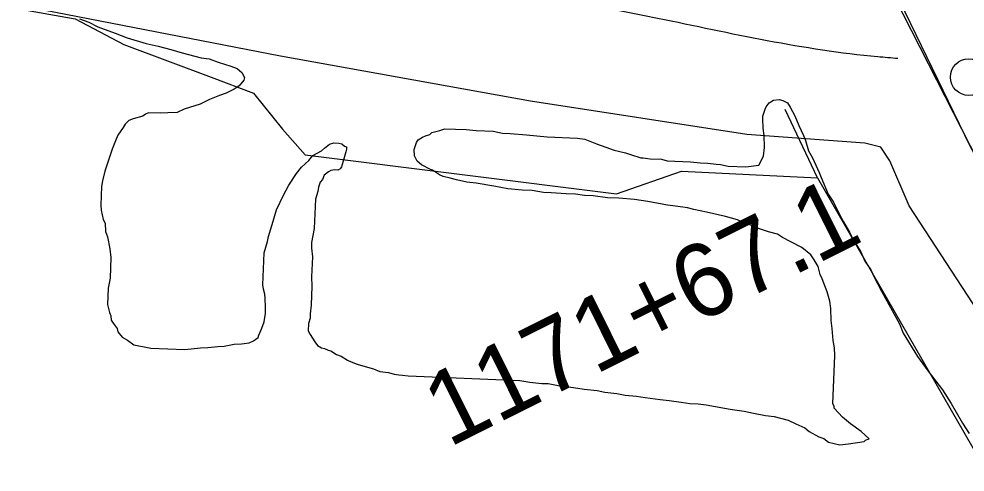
# Model space of a CAD drawing. Extents: x 3161514 to 3199414, y 831166 to 856601.
# Drawn here: x 3184047 to 3185339, y 837386 to 838004 of the extents above; entities that cross this region are included whole.
import ezdxf

# ---------------------------------------------------------------- set-up
doc = ezdxf.new("R2010")
doc.units = 0
for name, color, linetype in [('V-LEVE-TOET', 7, 'Continuous'), ('V-RAIL-TRAK', 7, 'Continuous'), ('V-ROAD-CNTR', 7, 'Continuous'), ('V-SITE-VEGE', 7, 'Continuous'), ('V-SURV-IDEN', 7, 'Continuous'), ('V-SURV-LINE', 7, 'Continuous'), ('V-TOPO-SHOR', 7, 'Continuous')]:
    doc.layers.add(name, color=color, linetype=linetype)

msp = doc.modelspace()

# ---------------------------------------------------------------- linework, layer by layer
at = {"layer": 'V-LEVE-TOET'}
msp.add_lwpolyline([(3185479.9, 837402), (3185378.5, 837572.4), (3185263.2, 837749.1), (3185236.4, 837810.4), (3185224.1, 837829.2), (3185202.7, 837834.6), (3185041.5, 837846.4), (3184746, 837891.8), (3184404.6, 837953.3), (3183911.8, 838049.4), (3183641.4, 838109.2), (3183369.5, 838165.1), (3183020.2, 838213.8), (3182646.2, 838283.9), (3182335, 838338.5), (3181981.1, 838407.4), (3181709.1, 838448.9), (3181476.7, 838488.3), (3181216.9, 838495.2), (3181043.3, 838497.2), (3180895.4, 838492), (3180760.8, 838480.3)], dxfattribs=at)
at = {"layer": 'V-RAIL-TRAK'}
msp.add_line((3184059.2, 840354.1), (3185467.8, 837592.3), dxfattribs=at)
at = {"layer": 'V-ROAD-CNTR'}
msp.add_lwpolyline([(3182510, 843255.2), (3182750, 842829.8), (3182962.8, 842459.6), (3183082.3, 842242.1), (3183216.7, 842004.2), (3183348.4, 841767.1), (3183502.7, 841469.7), (3183666.2, 841147.6), (3183851.3, 840779.3), (3184016.5, 840444.7), (3184210.8, 840064.8), (3184373.6, 839736.8), (3184597.6, 839309.2), (3184736.6, 839033.3), (3184901.3, 838718.9), (3185039.4, 838447.7), (3185242.5, 838044.4), (3185345.9, 837830.9), (3185543.6, 837469.6), (3185705.5, 837185.2), (3185948.9, 836754.5), (3186048.4, 836579.3)], dxfattribs=at)
msp.add_spline([(3185247.7, 837950), (3185220.1, 837952.3), (3184919.5, 838004.8), (3184339.6, 838108.5), (3183779, 838207.2), (3183367, 838284.1), (3182794.1, 838383.3), (3182428.7, 838447.8), (3182275.5, 838472.5), (3181998.8, 838523), (3181803.1, 838555.1), (3181641.5, 838586.6), (3181550.7, 838598.2), (3181445.6, 838611.4), (3181325.6, 838620), (3181174.8, 838631.9), (3181016.7, 838639.1), (3180880.4, 838632.5), (3180707.8, 838613), (3180579.6, 838596.6), (3180431.4, 838569.9), (3180332.4, 838547.3), (3180171.1, 838506.1), (3180026.7, 838458.9), (3179877.5, 838403.8), (3179654.2, 838294.6), (3179462.8, 838196.9), (3179346.3, 838121.9), (3179173.3, 838003.7), (3178965.2, 837857.6), (3178757.9, 837712.7), (3178391.8, 837460.5), (3178085.3, 837254.5), (3177675.2, 836977.6), (3177220.5, 836675.6), (3177123, 836609.3)], degree=3, dxfattribs=at)
at = {"layer": 'V-SITE-VEGE'}
for p, q in [((3184130.2, 838004), (3184142.7, 837999.7)), ((3184142.7, 837999.7), (3184155.1, 837993.4)), ((3184155.1, 837993.4), (3184179, 837984.6)), ((3184179, 837984.6), (3184195.3, 837978.2)), ((3184195.3, 837978.2), (3184221.2, 837970.4)), ((3184221.2, 837970.4), (3184237.6, 837966.8)), ((3184237.6, 837966.8), (3184255, 837962.2)), ((3184255, 837962.2), (3184270.3, 837957.8)), ((3184270.3, 837957.8), (3184296.3, 837950.9)), ((3184296.3, 837950.9), (3184307, 837949.5)), ((3184307, 837949.5), (3184319.4, 837945.2)), ((3184319.4, 837945.2), (3184336.7, 837939.6)), ((3184336.7, 837939.6), (3184345.4, 837936.4)), ((3184345.4, 837936.4), (3184352, 837931.2)), ((3184352, 837931.2), (3184355.6, 837924.3)), ((3184354.5, 837920.5), (3184348.3, 837912.9)), ((3184355.6, 837924.3), (3184354.5, 837920.5)), ((3184330.4, 837902.9), (3184321.5, 837899.4)), ((3184341.3, 837908.3), (3184330.4, 837902.9)), ((3184348.3, 837912.9), (3184341.3, 837908.3)), ((3184307.7, 837894.1), (3184294.8, 837887.8)), ((3184321.5, 837899.4), (3184307.7, 837894.1)), ((3185067.7, 837884), (3185071.8, 837889.6)), ((3185071.8, 837889.6), (3185077.8, 837893.3)), ((3185077.8, 837893.3), (3185085.6, 837894)), ((3185085.6, 837894), (3185090.4, 837892.8)), ((3185090.4, 837892.8), (3185097.1, 837889.6)), ((3185097.1, 837889.6), (3185100.7, 837883.6)), ((3184224.4, 837875.9), (3184220.4, 837874.1)), ((3184240.9, 837875.3), (3184224.4, 837875.9)), ((3184250.6, 837875.9), (3184240.9, 837875.3)), ((3184263.3, 837876.4), (3184250.6, 837875.9)), ((3184273.2, 837880.8), (3184263.3, 837876.4)), ((3184294.8, 837887.8), (3184273.2, 837880.8)), ((3185063.3, 837871.5), (3185066.6, 837881.1)), ((3185066.6, 837881.1), (3185067.7, 837884)), ((3185100.7, 837883.6), (3185107.1, 837871.7)), ((3184197.7, 837865.3), (3184192.7, 837860.6)), ((3184203.6, 837868), (3184197.7, 837865.3)), ((3184216.4, 837871.4), (3184203.6, 837868)), ((3184220.4, 837874.1), (3184216.4, 837871.4)), ((3185063.2, 837867.6), (3185063.3, 837871.5)), ((3185063.6, 837854.9), (3185063.2, 837867.6)), ((3185107.1, 837871.7), (3185112.4, 837858.9)), ((3184189.6, 837855.9), (3184182.4, 837845.5)), ((3184192.7, 837860.6), (3184189.6, 837855.9)), ((3184611.3, 837849.2), (3184622.1, 837851.7)), ((3184622.1, 837851.7), (3184629, 837854.3)), ((3184629, 837854.3), (3184658.1, 837853.2)), ((3184658.1, 837853.2), (3184671.7, 837851.7)), ((3184671.7, 837851.7), (3184695, 837850.8)), ((3184695, 837850.8), (3184707.5, 837848.4)), ((3185065.2, 837845.2), (3185063.6, 837854.9)), ((3185112.4, 837858.9), (3185118.7, 837845)), ((3184179.1, 837837.8), (3184174.8, 837826.3)), ((3184182.4, 837845.5), (3184179.1, 837837.8)), ((3184590.3, 837835.4), (3184592.4, 837839.2)), ((3184592.4, 837839.2), (3184598.4, 837842.9)), ((3184598.4, 837842.9), (3184602.4, 837844.7)), ((3184602.4, 837844.7), (3184608.3, 837846.4)), ((3184608.3, 837846.4), (3184611.3, 837849.2)), ((3184707.5, 837848.4), (3184718.2, 837848)), ((3184718.2, 837848), (3184740.5, 837846.1)), ((3184740.5, 837846.1), (3184768.6, 837843.1)), ((3184768.6, 837843.1), (3184810.3, 837841.5)), ((3184810.3, 837841.5), (3184820, 837840.1)), ((3184820, 837840.1), (3184836.3, 837833.6)), ((3185065.5, 837828.6), (3185065.2, 837845.2)), ((3185118.7, 837845), (3185121.3, 837838.1)), ((3185121.3, 837838.1), (3185125.6, 837824.3)), ((3184174.8, 837826.3), (3184172.6, 837819.6)), ((3184448.7, 837817.6), (3184460.6, 837824)), ((3184460.6, 837824), (3184464.6, 837827.7)), ((3184464.6, 837827.7), (3184471.6, 837833.2)), ((3184471.6, 837833.2), (3184477.5, 837835)), ((3184477.5, 837835), (3184484.3, 837834.7)), ((3184484.3, 837834.7), (3184488.2, 837833.6)), ((3184488.2, 837833.6), (3184491.9, 837830.5)), ((3184491.9, 837830.5), (3184494.8, 837829.4)), ((3184494.7, 837826.5), (3184493.6, 837822.7)), ((3184494.8, 837829.4), (3184494.7, 837826.5)), ((3184587, 837825.8), (3184590.3, 837835.4)), ((3184587.7, 837817.1), (3184587, 837825.8)), ((3184836.3, 837833.6), (3184848.7, 837829.3)), ((3184848.7, 837829.3), (3184860.2, 837824.9)), ((3184860.2, 837824.9), (3184875.6, 837821.4)), ((3185064.1, 837817), (3185065.5, 837828.6)), ((3185125.6, 837824.3), (3185131.1, 837814.4)), ((3184172.6, 837819.6), (3184168.2, 837807.1)), ((3184433.5, 837801.7), (3184443.5, 837811)), ((3184443.5, 837811), (3184448.7, 837817.6)), ((3184491.3, 837813), (3184487.9, 837802.5)), ((3184493.6, 837822.7), (3184491.3, 837813)), ((3184591.3, 837810.1), (3184587.7, 837817.1)), ((3184875.6, 837821.4), (3184882.4, 837819.2)), ((3184882.4, 837819.2), (3184896.8, 837814.8)), ((3184896.8, 837814.8), (3184899.7, 837814.6)), ((3184899.7, 837814.6), (3184909.4, 837813.3)), ((3184909.4, 837813.3), (3184924.9, 837812.7)), ((3184924.9, 837812.7), (3184932.6, 837810.5)), ((3185057.8, 837804.6), (3185064.1, 837817)), ((3185131.1, 837814.4), (3185140, 837794.6)), ((3184168.2, 837807.1), (3184164.9, 837796.6)), ((3184426.3, 837793.2), (3184433.5, 837801.7)), ((3184479, 837798), (3184473.1, 837797.2)), ((3184482.9, 837797.8), (3184479, 837798)), ((3184485.9, 837799.6), (3184482.9, 837797.8)), ((3184487.9, 837802.5), (3184485.9, 837799.6)), ((3184596.9, 837805), (3184591.3, 837810.1)), ((3184609.3, 837798.7), (3184596.9, 837805)), ((3184612.2, 837797.6), (3184609.3, 837798.7)), ((3184932.6, 837810.5), (3184964.6, 837809.2)), ((3184964.6, 837809.2), (3184978.2, 837807.7)), ((3184978.2, 837807.7), (3184987.9, 837807.3)), ((3184987.9, 837807.3), (3184999.5, 837805.9)), ((3184999.5, 837805.9), (3185005.3, 837805.7)), ((3185005.3, 837805.7), (3185015.9, 837803.3)), ((3185015.9, 837803.3), (3185040.2, 837802.4)), ((3185040.2, 837802.4), (3185057.8, 837804.6)), ((3184164.9, 837796.6), (3184161.5, 837783.1)), ((3184416, 837777.1), (3184426.3, 837793.2)), ((3184464.1, 837790.8), (3184462, 837785)), ((3184470.2, 837795.4), (3184464.1, 837790.8)), ((3184473.1, 837797.2), (3184470.2, 837795.4)), ((3184621.7, 837791.4), (3184612.2, 837797.6)), ((3184626.5, 837789.3), (3184621.7, 837791.4)), ((3184636.1, 837787), (3184626.5, 837789.3)), ((3184644.8, 837784.7), (3184636.1, 837787)), ((3185140, 837794.6), (3185142.7, 837787.7)), ((3185142.7, 837787.7), (3185152.5, 837764.9)), ((3184160.2, 837775.4), (3184159.2, 837750.1)), ((3184161.5, 837783.1), (3184160.2, 837775.4)), ((3184408.6, 837763.7), (3184416, 837777.1)), ((3184456.7, 837774.5), (3184455.5, 837768.7)), ((3184458.9, 837781.2), (3184456.7, 837774.5)), ((3184462, 837785), (3184458.9, 837781.2)), ((3184659.2, 837781.2), (3184644.8, 837784.7)), ((3184671.8, 837779.8), (3184659.2, 837781.2)), ((3184695.9, 837775.9), (3184671.8, 837779.8)), ((3184715.2, 837772.2), (3184695.9, 837775.9)), ((3184734.6, 837770.5), (3184715.2, 837772.2)), ((3184399.1, 837743.7), (3184408.6, 837763.7)), ((3184455.5, 837768.7), (3184452.2, 837758.2)), ((3184748.2, 837770), (3184734.6, 837770.5)), ((3184763.7, 837767.4), (3184748.2, 837770)), ((3184774.4, 837767), (3184763.7, 837767.4)), ((3184794.7, 837765.3), (3184774.4, 837767)), ((3184807.3, 837764.8), (3184794.7, 837765.3)), ((3184819.9, 837763.3), (3184807.3, 837764.8)), ((3184831.6, 837762.8), (3184819.9, 837763.3)), ((3184850.9, 837760.2), (3184831.6, 837762.8)), ((3184866.4, 837759.5), (3184850.9, 837760.2)), ((3184887.8, 837757.7), (3184866.4, 837759.5)), ((3185152.5, 837764.9), (3185159.9, 837754)), ((3184159.2, 837750.1), (3184159.9, 837743.3)), ((3184452.2, 837758.2), (3184450.6, 837718.4)), ((3184906.1, 837755.1), (3184887.8, 837757.7)), ((3184933.2, 837750.1), (3184906.1, 837755.1)), ((3184943.8, 837748.8), (3184933.2, 837750.1)), ((3184960.2, 837746.2), (3184943.8, 837748.8)), ((3185159.9, 837754), (3185167.9, 837737.1)), ((3184159.9, 837743.3), (3184162.3, 837730.5)), ((3184394.6, 837728.3), (3184399.1, 837743.7)), ((3184968.9, 837743.9), (3184960.2, 837746.2)), ((3184986.2, 837740.3), (3184968.9, 837743.9)), ((3185012.3, 837734.4), (3184986.2, 837740.3)), ((3185028.6, 837729.9), (3185012.3, 837734.4)), ((3185167.9, 837737.1), (3185173.4, 837727.2)), ((3184162.3, 837730.5), (3184165.1, 837725.6)), ((3184165.1, 837725.6), (3184165.6, 837713.9)), ((3184388, 837707.2), (3184394.6, 837728.3)), ((3185035.3, 837726.7), (3185028.6, 837729.9)), ((3185047.8, 837722.4), (3185035.3, 837726.7)), ((3185054.5, 837719.2), (3185047.8, 837722.4)), ((3185173.4, 837727.2), (3185181.6, 837713.3)), ((3184165.6, 837713.9), (3184168.2, 837707)), ((3184450.6, 837718.4), (3184447, 837699.1)), ((3185070.8, 837713.7), (3185054.5, 837719.2)), ((3185083.3, 837710.3), (3185070.8, 837713.7)), ((3185089.9, 837706.1), (3185083.3, 837710.3)), ((3185181.6, 837713.3), (3185187, 837702.3)), ((3184168.2, 837707), (3184171.5, 837690.3)), ((3184382.2, 837685), (3184386.7, 837700.4)), ((3184386.7, 837700.4), (3184388, 837707.2)), ((3184447, 837699.1), (3184446.7, 837691.3)), ((3185101.4, 837699.8), (3185089.9, 837706.1)), ((3185116.6, 837692.4), (3185101.4, 837699.8)), ((3185187, 837702.3), (3185197.1, 837686.4)), ((3184171.5, 837690.3), (3184172.9, 837678.6)), ((3184380.5, 837641.4), (3184382.2, 837685)), ((3184446.7, 837691.3), (3184448.1, 837679.6)), ((3185128.9, 837682.2), (3185116.6, 837692.4)), ((3185133.5, 837675.3), (3185128.9, 837682.2)), ((3185197.1, 837686.4), (3185202.4, 837673.6)), ((3184172.9, 837678.6), (3184171.9, 837650.4)), ((3184448.1, 837679.6), (3184447.1, 837652.4)), ((3185138.9, 837666.3), (3185133.5, 837675.3)), ((3185202.4, 837673.6), (3185210.7, 837661.6)), ((3185141.4, 837655.5), (3185138.9, 837666.3)), ((3185210.7, 837661.6), (3185215.2, 837651.7)), ((3184171.9, 837650.4), (3184169.4, 837636.9)), ((3184447.1, 837652.4), (3184447.6, 837639.7)), ((3185144.1, 837649.6), (3185141.4, 837655.5)), ((3185151.2, 837631.8), (3185144.1, 837649.6)), ((3185215.2, 837651.7), (3185225.1, 837632.8)), ((3184169.4, 837636.9), (3184168.5, 837614.6)), ((3184381.3, 837635.5), (3184380.5, 837641.4)), ((3184383, 837628.6), (3184381.3, 837635.5)), ((3184447.6, 837639.7), (3184446.6, 837613.5)), ((3185154.6, 837619), (3185151.2, 837631.8)), ((3185225.1, 837632.8), (3185249.7, 837588.1)), ((3184383.7, 837622.8), (3184383, 837628.6)), ((3184384.2, 837611.1), (3184383.7, 837622.8)), ((3185156.2, 837609.2), (3185154.6, 837619)), ((3184168.5, 837614.6), (3184171, 837603.8)), ((3184383.9, 837602.3), (3184384.2, 837611.1)), ((3184446.6, 837613.5), (3184445.1, 837601.9)), ((3185156.5, 837592.7), (3185156.2, 837609.2)), ((3184171, 837603.8), (3184172.8, 837598.9)), ((3184172.8, 837598.9), (3184173.5, 837593)), ((3184173.5, 837593), (3184176.3, 837589)), ((3184382.5, 837590.7), (3184383.9, 837602.3)), ((3184444.9, 837596.1), (3184442.7, 837588.4)), ((3184445.1, 837601.9), (3184444.9, 837596.1)), ((3185158, 837581.9), (3185156.5, 837592.7)), ((3184176.3, 837589), (3184181.8, 837582)), ((3184181.8, 837582), (3184182.6, 837577.1)), ((3184375, 837572.5), (3184379.2, 837582.1)), ((3184379.2, 837582.1), (3184382.5, 837590.7)), ((3184442.7, 837588.4), (3184442.3, 837578.7)), ((3184442.3, 837578.7), (3184445, 837573.7)), ((3185159.3, 837565.4), (3185158, 837581.9)), ((3185249.7, 837588.1), (3185255, 837575.2)), ((3184182.6, 837577.1), (3184188.2, 837570.1)), ((3184188.2, 837570.1), (3184195.8, 837565.9)), ((3184195.8, 837565.9), (3184204.3, 837559.7)), ((3184367.9, 837565), (3184373.9, 837569.7)), ((3184373.9, 837569.7), (3184375, 837572.5)), ((3184445, 837573.7), (3184451.4, 837563.7)), ((3185255, 837575.2), (3185274.2, 837543.4)), ((3184204.3, 837559.7), (3184209.1, 837558.6)), ((3184209.1, 837558.6), (3184220.7, 837556.2)), ((3184220.7, 837556.2), (3184227.5, 837554.9)), ((3184227.5, 837554.9), (3184274, 837553.1)), ((3184274, 837553.1), (3184295.5, 837555.2)), ((3184295.5, 837555.2), (3184305.3, 837555.8)), ((3184305.3, 837555.8), (3184318.9, 837557.2)), ((3184318.9, 837557.2), (3184327.7, 837557.9)), ((3184327.7, 837557.9), (3184341.4, 837560.2)), ((3184341.4, 837560.2), (3184351.2, 837560.8)), ((3184351.2, 837560.8), (3184361.9, 837562.4)), ((3184361.9, 837562.4), (3184367.9, 837565)), ((3184451.4, 837563.7), (3184455.1, 837558.7)), ((3184455.1, 837558.7), (3184460.8, 837555.6)), ((3184460.8, 837555.6), (3184464.7, 837554.5)), ((3184464.7, 837554.5), (3184469.5, 837552.3)), ((3185160.9, 837555.6), (3185159.3, 837565.4)), ((3185161.4, 837544.9), (3185160.9, 837555.6)), ((3184469.5, 837552.3), (3184473.3, 837551.2)), ((3184473.3, 837551.2), (3184480.9, 837546.1)), ((3184480.9, 837546.1), (3184487.6, 837543.9)), ((3184487.6, 837543.9), (3184496.1, 837538.7)), ((3185158.9, 837478.8), (3185161.4, 837544.9)), ((3185274.2, 837543.4), (3185288.9, 837523.4)), ((3184496.1, 837538.7), (3184500.9, 837536.5)), ((3184500.9, 837536.5), (3184509.5, 837533.3)), ((3184509.5, 837533.3), (3184517.2, 837531)), ((3184517.2, 837531), (3184531.6, 837526.6)), ((3184531.6, 837526.6), (3184540.3, 837523.3)), ((3184540.3, 837523.3), (3184551.9, 837521.9)), ((3184551.9, 837521.9), (3184559.6, 837519.7)), ((3184559.6, 837519.7), (3184566.3, 837518.4)), ((3184566.3, 837518.4), (3184571.2, 837518.2)), ((3184571.2, 837518.2), (3184578.9, 837517)), ((3184578.9, 837517), (3184731.3, 837511)), ((3185288.9, 837523.4), (3185308.4, 837498.3)), ((3184731.3, 837511), (3184744.9, 837508.6)), ((3184744.9, 837508.6), (3184761.3, 837506.9)), ((3184761.3, 837506.9), (3184770.1, 837506.6)), ((3184770.1, 837506.6), (3184783.6, 837504.1)), ((3184783.6, 837504.1), (3184804.9, 837501.4)), ((3184804.9, 837501.4), (3184819.3, 837498.9)), ((3184819.3, 837498.9), (3184836.8, 837497.2)), ((3184836.8, 837497.2), (3184847.4, 837494.9)), ((3184847.4, 837494.9), (3184863.9, 837493.2)), ((3184863.9, 837493.2), (3184875.4, 837490.8)), ((3184875.4, 837490.8), (3184890.9, 837489.3)), ((3184890.9, 837489.3), (3184902.5, 837487.8)), ((3185308.4, 837498.3), (3185320.3, 837479.4)), ((3184902.5, 837487.8), (3184922.8, 837485.1)), ((3184922.8, 837485.1), (3184935.4, 837483.6)), ((3184935.4, 837483.6), (3184951.9, 837481.1)), ((3184951.9, 837481.1), (3184963.5, 837479.6)), ((3184963.5, 837479.6), (3184975.1, 837479.2)), ((3184975.1, 837479.2), (3184985.8, 837477.8)), ((3184985.8, 837477.8), (3185018.6, 837471.7)), ((3185160.7, 837475.9), (3185158.9, 837478.8)), ((3185160.6, 837472.9), (3185160.7, 837475.9)), ((3185320.3, 837479.4), (3185335.8, 837452.5)), ((3185018.6, 837471.7), (3185037.9, 837469)), ((3185037.9, 837469), (3185050.5, 837466.5)), ((3185050.5, 837466.5), (3185066.9, 837463)), ((3185066.9, 837463), (3185078.5, 837461.6)), ((3185171.8, 837460.8), (3185160.6, 837472.9)), ((3185078.5, 837461.6), (3185097.7, 837456.9)), ((3185097.7, 837456.9), (3185108.2, 837451.6)), ((3185108.2, 837451.6), (3185120.7, 837446.3)), ((3185183.1, 837451.6), (3185171.8, 837460.8)), ((3185197.3, 837441.4), (3185183.1, 837451.6)), ((3185335.8, 837452.5), (3185345, 837438.5)), ((3185120.7, 837446.3), (3185126.3, 837441.2)), ((3185126.3, 837441.2), (3185139.6, 837433.9)), ((3185208.6, 837431.2), (3185197.3, 837441.4)), ((3185139.6, 837433.9), (3185146.3, 837431.7)), ((3185146.3, 837431.7), (3185152.9, 837426.6)), ((3185152.9, 837426.6), (3185168.4, 837423)), ((3185168.4, 837423), (3185180.1, 837424.5)), ((3185180.1, 837424.5), (3185201.6, 837427.6)), ((3185201.6, 837427.6), (3185203.6, 837429.5)), ((3185203.6, 837429.5), (3185205.6, 837430.4)), ((3185205.6, 837430.4), (3185208.6, 837431.2))]:
    msp.add_line(p, q, dxfattribs=at)
at = {"layer": 'V-SURV-LINE'}
msp.add_circle((3185344.4, 837924.7), 25, dxfattribs=at)
at = {"layer": 'V-TOPO-SHOR'}
for points in [[(3180751.3, 838473.6), (3181118.7, 838469.2), (3181428.6, 838469.2), (3181627.7, 838442.6), (3182141.2, 838354.1), (3182402.4, 838309.8), (3184124.2, 838004.4), (3184190.6, 837969), (3184310.1, 837924.7), (3184367.7, 837902.6), (3184407.5, 837853.9), (3184438.5, 837818.5), (3184863.4, 837765.4), (3184952, 837796.4), (3185137.9, 837787.5), (3185093.6, 837880.5)], [(3185137.9, 837787.5), (3185558.4, 837057.2), (3185766.4, 836698.6), (3185828.4, 836579.1)]]:
    msp.add_lwpolyline(points, dxfattribs=at)

# ---------------------------------------------------------------- texts
at = {"layer": 'V-SURV-IDEN'}
msp.add_text('1171+67.1', height=100, rotation=26.4925, dxfattribs=at).set_placement((3184634.1, 837418.8))

doc.saveas('drawing.dxf')
